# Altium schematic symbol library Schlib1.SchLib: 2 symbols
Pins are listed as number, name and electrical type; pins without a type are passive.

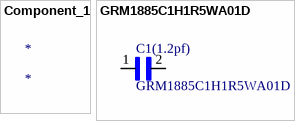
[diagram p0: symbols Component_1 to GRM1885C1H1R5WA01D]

## Component_1
designator *

## GRM1885C1H1R5WA01D
designator C1(1.2pf)
CAP 1.5PF 50VDC C0G 0.05PF SMD 0603 PAPER TAPE
footprint CAPC1608X90N
pins: 1, 2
